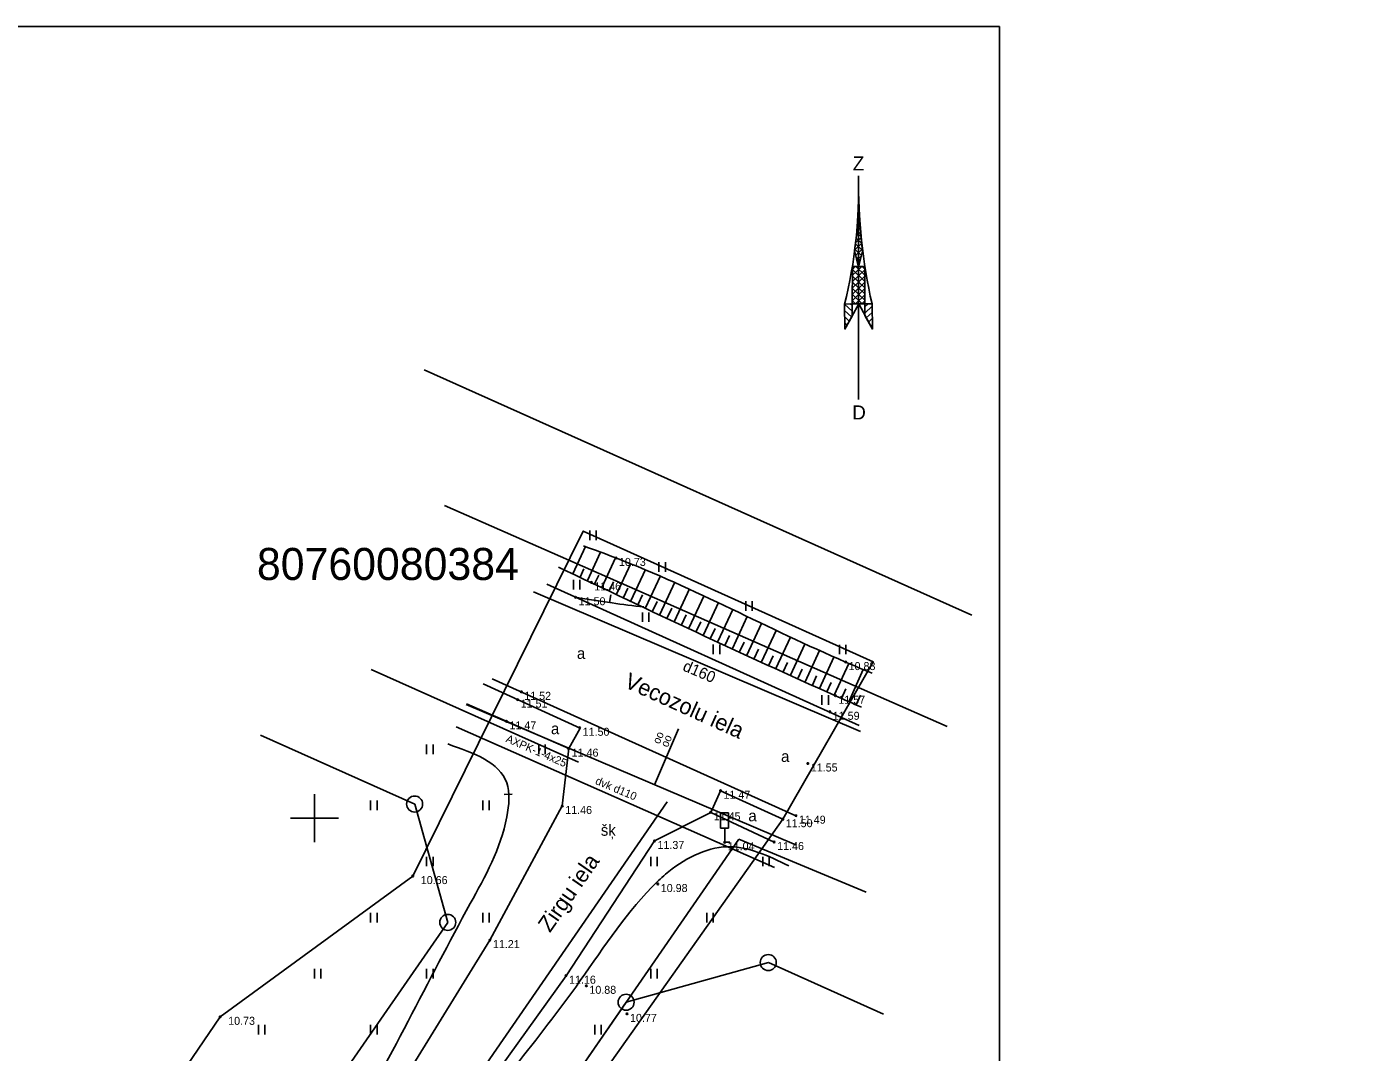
# Model space of a CAD drawing. Extents: x 503353 to 504004, y 304662 to 305049.
# Drawn here: x 503632 to 503715.2, y 304985.4 to 305049.4 of the extents above; entities that cross this region are included whole.
import ezdxf

# ---------------------------------------------------------------- set-up
doc = ezdxf.new("R2010")
doc.units = 0
for name, color, linetype in [('24', 7, 'Continuous'), ('25', 7, 'Continuous'), ('59', 7, 'Continuous'), ('APGR_ELEM_####_####_#', 7, 'Continuous'), ('APGR_SARK_####_####_#', 7, 'Continuous'), ('APGS_ACRL_####_####_#', 7, 'Continuous'), ('APGS_VADP_ZSPR_####_#', 7, 'Continuous'), ('APGS_VADP_ZSPR_TKST_#', 7, 'Continuous'), ('CELI_CMAL_####_####_#', 7, 'Continuous'), ('CELI_CSEG_####_TKST_#', 7, 'Continuous'), ('CELI_ELEM_####_####_#', 7, 'Continuous'), ('CELI_IELA_####_TKST_#', 7, 'Continuous'), ('CELI_SEGL_####_####_#', 7, 'Continuous'), ('GEOD_ELEM_####_####_#', 7, 'Continuous'), ('RAMI_PLAN_####_TKST_#', 7, 'Continuous'), ('RAMI_UZMR_####_####_#', 7, 'Continuous'), ('RELJ_AATZ_####_TKST_#', 7, 'Continuous'), ('RELJ_ELEM_####_####_#', 7, 'Continuous'), ('RELJ_HORZ_PAMT_####_#', 7, 'Continuous'), ('RELJ_NOGA_####_####_#', 7, 'Continuous'), ('RELJ_NOGL_####_####_#', 7, 'Continuous'), ('SAKK_IZVK_####_TKST_#', 7, 'Continuous'), ('SAKK_KKAN_####_####_#', 7, 'Continuous'), ('TERT_ELEM_####_####_#', 7, 'Continuous'), ('UDTK_VADP_UDEN_####_#', 7, 'Continuous'), ('UDTK_VADP_UDEN_TKST_#', 7, 'Continuous')]:
    doc.layers.add(name, color=color, linetype=linetype)

msp = doc.modelspace()

# ---------------------------------------------------------------- linework, layer by layer
at = {"layer": '24'}
for p, q in [((503653.541, 305009.291), (503666.475, 305003.51)), ((503655.169, 304967.847), (503676.504, 304998.703)), ((503676.504, 304998.703), (503684.443, 304995.386))]:
    msp.add_line(p, q, dxfattribs=at)
at = {"layer": '25'}
for p, q in [((503658.122, 305019.539), (503689.517, 305005.723)), ((503672.032, 305001.026), (503595.592, 304890.48))]:
    msp.add_line(p, q, dxfattribs=at)
at = {"layer": 'APGR_ELEM_####_####_#'}
for centre in [(503656.25, 305000.89), (503658.32, 304993.5), (503678.34, 304990.99), (503669.46, 304988.51)]:
    msp.add_circle(centre, 0.5, dxfattribs=at)
at = {"layer": 'APGR_SARK_####_####_#'}
for p, q in [((503656.846, 305028.015), (503691.055, 305012.69)), ((503646.625, 305005.199), (503656.252, 305000.886)), ((503658.316, 304993.498), (503656.252, 305000.886)), ((503595.509, 304902.665), (503658.316, 304993.498)), ((503678.343, 304990.99), (503669.455, 304988.508)), ((503678.343, 304990.99), (503685.526, 304987.772)), ((503669.455, 304988.508), (503606.367, 304897.269))]:
    msp.add_line(p, q, dxfattribs=at)
at = {"layer": 'APGS_ACRL_####_####_#'}
msp.add_line((503678.721, 304996.933), (503658.853, 305005.718), dxfattribs=at)
at = {"layer": 'APGS_VADP_ZSPR_####_#'}
msp.add_line((503678.721, 304996.933), (503658.853, 305005.718), dxfattribs=at)
at = {"layer": 'CELI_CMAL_####_####_#'}
for points in [[(503664.508, 305014.617), (503684.019, 305005.802)], [(503661.094, 305008.716), (503680.064, 305000.162)], [(503659.487, 305007.152), (503665.873, 305004.349)], [(503605.515, 304909.352), (503607.775, 304912.97), (503627.397, 304941.5), (503635.622, 304953.341), (503652.6, 304978.844), (503660.954, 304992.392), (503665.471, 305000.768), (503665.873, 305004.349)], [(503674.743, 305000.37), (503671.232, 304998.583), (503665.707, 304990.166), (503656.075, 304976.73), (503638.511, 304950.933)], [(503674.743, 305000.37), (503678.708, 304998.517)]]:
    msp.add_lwpolyline(points, dxfattribs=at)
at = {"layer": 'CELI_ELEM_####_####_#'}
for p, q in [((503675.864, 305000.348), (503675.364, 305000.348)), ((503675.364, 304999.379), (503675.364, 305000.348)), ((503675.864, 304999.379), (503675.864, 305000.348)), ((503675.864, 304999.379), (503675.364, 304999.379)), ((503675.618, 304999.379), (503675.618, 304998.501)), ((503675.618, 304998.501), (503675.933, 304998.501))]:
    msp.add_line(p, q, dxfattribs=at)
at = {"layer": 'CELI_SEGL_####_####_#'}
for points in [[(503660.523, 305008.403), (503666.595, 305005.618), (503665.873, 305004.349)], [(503679.244, 304999.942), (503675.357, 305001.719), (503674.743, 305000.37)]]:
    msp.add_lwpolyline(points, dxfattribs=at)
at = {"layer": 'GEOD_ELEM_####_####_#'}
for p, q in [((503650, 305001.5), (503650, 305000)), ((503648.5, 305000), (503650, 305000)), ((503650, 305000), (503650, 304998.5)), ((503650, 305000), (503651.5, 305000))]:
    msp.add_line(p, q, dxfattribs=at)
at = {"layer": 'RAMI_PLAN_####_TKST_#'}
for p, q in [((503683.972, 305040.12), (503683.972, 305026.15)), ((503683.976, 305038.419), (503683.998, 305038.397)), ((503683.904, 305037.21), (503684.051, 305037.343)), ((503683.93, 305037.618), (503684.032, 305037.717)), ((503683.933, 305037.682), (503684.04, 305037.579)), ((503683.95, 305038.027), (503684.013, 305038.086)), ((503683.952, 305038.049), (503684.017, 305037.989)), ((503683.837, 305036.365), (503684.11, 305036.627)), ((503683.856, 305036.591), (503684.136, 305036.323)), ((503683.872, 305036.79), (503684.08, 305036.986)), ((503683.885, 305036.951), (503684.102, 305036.745)), ((503683.913, 305037.309), (503684.066, 305037.167)), ((503683.738, 305035.494), (503684.173, 305035.909)), ((503683.78, 305035.884), (503684.224, 305035.461)), ((503683.786, 305035.932), (503684.142, 305036.268)), ((503683.82, 305036.235), (503684.175, 305035.898)), ((503683.742, 305035.536), (503684.156, 305035.139)), ((503683.799, 305035.163), (503684.214, 305035.563)), ((503683.819, 305035.074), (503684.075, 305034.827)), ((503683.872, 305034.846), (503684.148, 305035.109)), ((503683.583, 305033.499), (503684.37, 305034.247)), ((503683.585, 305033.889), (503684.185, 305034.458)), ((503683.59, 305034.279), (503683.776, 305034.458)), ((503683.59, 305034.266), (503684.372, 305033.523)), ((503683.797, 305034.458), (503684.372, 305033.911)), ((503683.934, 305034.572), (503683.993, 305034.516)), ((503683.944, 305034.527), (503684.016, 305034.598)), ((503684.205, 305034.458), (503684.37, 305034.3)), ((503683.575, 305032.712), (503684.372, 305033.473)), ((503683.579, 305033.106), (503684.372, 305033.861)), ((503683.583, 305033.499), (503684.374, 305032.745)), ((503683.585, 305033.879), (503684.374, 305033.134)), ((503683.571, 305032.321), (503684.374, 305033.084)), ((503683.571, 305032.341), (503683.791, 305032.134)), ((503683.575, 305032.728), (503684.2, 305032.134)), ((503683.579, 305033.112), (503684.376, 305032.355)), ((503683.782, 305032.134), (503684.374, 305032.696)), ((503683.102, 305032.1), (503683.124, 305030.551)), ((503683.105, 305032.1), (503683.569, 305031.664)), ((503683.108, 305031.709), (503683.536, 305031.308)), ((503683.124, 305030.551), (503683.985, 305032.125)), ((503683.483, 305032.129), (503683.57, 305032.047)), ((503683.985, 305032.125), (503684.843, 305030.551)), ((503684.188, 305032.134), (503684.376, 305032.311)), ((503684.374, 305031.553), (503684.824, 305031.978)), ((503684.376, 305031.94), (503684.572, 305032.129)), ((503684.462, 305031.245), (503684.827, 305031.597)), ((503684.843, 305030.551), (503684.82, 305032.125)), ((503683.113, 305031.316), (503683.397, 305031.051)), ((503683.12, 305030.921), (503683.256, 305030.792)), ((503684.602, 305030.992), (503684.832, 305031.211)), ((503684.741, 305030.737), (503684.839, 305030.827)), ((503683.124, 305030.558), (503683.134, 305030.567)), ((503684.843, 305030.554), (503684.843, 305030.554))]:
    msp.add_line(p, q, dxfattribs=at)
for points in [[(503692.785, 305049.441), (503692.785, 304852.257), (503550.18, 304852.257), (503550.18, 305049.441)], [(503683.971, 305034.419), (503683.731, 305035.45), (503683.841, 305036.406), (503683.911, 305037.28), (503683.973, 305038.419), (503683.995, 305038.419), (503684.051, 305037.343), (503684.166, 305035.974), (503684.228, 305035.426)], [(503683.591, 305034.458), (503684.37, 305034.458), (503684.376, 305032.132), (503683.57, 305032.136)], [(503683.57, 305032.136), (503683.568, 305031.362), (503683.124, 305030.551), (503683.102, 305032.1)], [(503684.376, 305032.132), (503684.374, 305031.402), (503684.843, 305030.551), (503684.82, 305032.125)]]:
    msp.add_lwpolyline(points, close=True, dxfattribs=at)
for centre, major_axis, start_param, end_param in [((503651.639, 305039.236), (32.345, 0), 6.048896, 6.311872), ((503722.31, 305039.752), (-38.341, 0), 6.273156, 6.494161)]:
    msp.add_ellipse(centre, major_axis=major_axis, ratio=0.950423, start_param=start_param, end_param=end_param, dxfattribs=at)
at = {"layer": 'RAMI_UZMR_####_####_#'}
msp.add_lwpolyline([(503825.923, 304784.828), (503697.433, 304847.709), (503608.51, 304889.842), (503606.524, 304897.202), (503679.244, 304999.942), (503684.897, 305009.76), (503666.777, 305017.939), (503656.134, 304996.39), (503644.103, 304987.6), (503600.987, 304924.263), (503587.985, 304916.668), (503422.237, 304989.372), (503408.615, 305023.495), (503368.776, 305020.183)], dxfattribs=at)
at = {"layer": 'RELJ_ELEM_####_####_#'}
for centre in [(503668.826, 305016.26), (503667.284, 305014.733), (503666.31, 305013.803), (503683.172, 305009.755), (503662.688, 305007.41), (503662.91, 305007.897), (503682.531, 305007.654), (503682.183, 305006.651), (503661.987, 305006.055), (503666.56, 305005.653), (503665.873, 305004.349), (503680.81, 305003.422), (503675.357, 305001.719), (503665.471, 305000.768), (503674.743, 305000.37), (503679.244, 304999.942), (503680.064, 305000.162), (503671.232, 304998.583), (503675.618, 304998.501), (503678.708, 304998.517), (503656.134, 304996.39), (503671.438, 304995.893), (503660.954, 304992.392), (503665.707, 304990.166), (503666.979, 304989.536), (503644.103, 304987.6), (503669.517, 304987.785)]:
    msp.add_circle(centre, 0.05, dxfattribs=at)
at = {"layer": 'RELJ_HORZ_PAMT_####_#'}
for p, q in [((503668.502, 305013.963), (503668.43, 305013.468)), ((503661.834, 305001.49), (503662.334, 305001.498))]:
    msp.add_line(p, q, dxfattribs=at)
for points in [[(503665.225, 305015.689), (503682.531, 305007.654), (503684.157, 305006.937)], [(503666.31, 305013.803), (503668.578, 305013.447), (503670.568, 305013.195)], [(503633.337, 304950.051), (503641.34, 304963.681), (503651.833, 304980), (503659.721, 304994.671), (503662.005, 305000.088), (503662.005, 305002.22), (503658.32, 305004.641)], [(503679.623, 304997.028), (503675.778, 304998.226), (503671.921, 304996.503), (503671.06, 304995.689), (503666.309, 304989.46), (503658.324, 304978.924), (503656.549, 304976.193), (503644.463, 304949.187)]]:
    msp.add_spline(points, degree=3, dxfattribs=at)
at = {"layer": 'RELJ_NOGA_####_####_#'}
for p, q in [((503666.132, 305015.267), (503666.921, 305016.963)), ((503667.038, 305014.845), (503667.864, 305016.615)), ((503667.945, 305014.422), (503668.806, 305016.267)), ((503668.85, 305013.998), (503669.745, 305015.91)), ((503665.225, 305015.689), (503665.226, 305015.69)), ((503665.679, 305015.478), (503665.679, 305015.478)), ((503666.585, 305015.056), (503666.828, 305015.576)), ((503667.492, 305014.634), (503667.745, 305015.176)), ((503669.756, 305013.575), (503670.674, 305015.535)), ((503670.662, 305013.151), (503671.596, 305015.145)), ((503668.398, 305014.21), (503668.661, 305014.774)), ((503669.303, 305013.786), (503669.575, 305014.368)), ((503671.568, 305012.727), (503672.511, 305014.742)), ((503672.473, 305012.303), (503673.421, 305014.328)), ((503670.209, 305013.363), (503670.487, 305013.957)), ((503671.115, 305012.939), (503671.397, 305013.541)), ((503673.379, 305011.879), (503674.326, 305013.905)), ((503674.285, 305011.456), (503675.229, 305013.475)), ((503672.02, 305012.515), (503672.304, 305013.121)), ((503672.926, 305012.091), (503673.211, 305012.699)), ((503675.191, 305011.033), (503676.128, 305013.041)), ((503676.098, 305010.611), (503677.026, 305012.606)), ((503673.832, 305011.667), (503674.116, 305012.274)), ((503674.738, 305011.244), (503675.02, 305011.849)), ((503677.005, 305010.189), (503677.924, 305012.17)), ((503677.912, 305009.769), (503678.822, 305011.737)), ((503675.644, 305010.822), (503675.924, 305011.422)), ((503676.551, 305010.4), (503676.828, 305010.996)), ((503678.82, 305009.35), (503679.723, 305011.307)), ((503679.728, 305008.932), (503680.626, 305010.884)), ((503677.458, 305009.979), (503677.733, 305010.571)), ((503678.366, 305009.559), (503678.637, 305010.148)), ((503680.638, 305008.515), (503681.531, 305010.471)), ((503681.547, 305008.1), (503682.443, 305010.067)), ((503679.274, 305009.141), (503679.544, 305009.727)), ((503680.183, 305008.723), (503680.451, 305009.309)), ((503682.458, 305007.687), (503683.36, 305009.676)), ((503683.372, 305007.281), (503684.255, 305009.3)), ((503681.092, 305008.308), (503681.36, 305008.896)), ((503682.003, 305007.894), (503682.272, 305008.487)), ((503682.914, 305007.483), (503683.18, 305008.085)), ((503683.83, 305007.081), (503684.096, 305007.688))]:
    msp.add_line(p, q, dxfattribs=at)
at = {"layer": 'RELJ_NOGL_####_####_#'}
msp.add_spline([(503666.787, 305017.013), (503668.826, 305016.26), (503683.172, 305009.755), (503684.835, 305009.056)], degree=3, dxfattribs=at)
at = {"layer": 'SAKK_IZVK_####_TKST_#'}
msp.add_line((503672.723, 305005.581), (503671.237, 305002.092), dxfattribs=at)
at = {"layer": 'SAKK_KKAN_####_####_#'}
for points in [[(503676.152, 305000), (503659.477, 305007.099)], [(503680.101, 304998.318), (503676.152, 305000)]]:
    msp.add_lwpolyline(points, dxfattribs=at)
at = {"layer": 'TERT_ELEM_####_####_#'}
for p, q in [((503667.197, 305017.363), (503667.197, 305017.963)), ((503667.597, 305017.363), (503667.597, 305017.963)), ((503671.511, 305015.401), (503671.511, 305016.001)), ((503671.911, 305015.401), (503671.911, 305016.001)), ((503666.172, 305014.284), (503666.172, 305014.884)), ((503666.572, 305014.284), (503666.572, 305014.884)), ((503676.94, 305012.953), (503676.94, 305013.553)), ((503677.34, 305012.953), (503677.34, 305013.553)), ((503670.486, 305012.26), (503670.486, 305012.86)), ((503670.886, 305012.26), (503670.886, 305012.86)), ((503674.903, 305010.257), (503674.903, 305010.857)), ((503675.303, 305010.257), (503675.303, 305010.857)), ((503682.791, 305010.242), (503682.791, 305010.842)), ((503683.191, 305010.242), (503683.191, 305010.842)), ((503681.691, 305007.092), (503681.691, 305007.692)), ((503682.091, 305007.092), (503682.091, 305007.692)), ((503657, 305004), (503657, 305004.6)), ((503657.4, 305004), (503657.4, 305004.6)), ((503664, 305004), (503664, 305004.6)), ((503664.4, 305004), (503664.4, 305004.6)), ((503653.5, 305000.5), (503653.5, 305001.1)), ((503653.9, 305000.5), (503653.9, 305001.1)), ((503660.5, 305000.5), (503660.5, 305001.1)), ((503660.9, 305000.5), (503660.9, 305001.1)), ((503657, 304997), (503657, 304997.6)), ((503657.4, 304997), (503657.4, 304997.6)), ((503671, 304997), (503671, 304997.6)), ((503671.4, 304997), (503671.4, 304997.6)), ((503678, 304997), (503678, 304997.6)), ((503678.4, 304997), (503678.4, 304997.6)), ((503653.5, 304993.5), (503653.5, 304994.1)), ((503653.9, 304993.5), (503653.9, 304994.1)), ((503660.5, 304993.5), (503660.5, 304994.1)), ((503660.9, 304993.5), (503660.9, 304994.1)), ((503674.5, 304993.5), (503674.5, 304994.1)), ((503674.9, 304993.5), (503674.9, 304994.1)), ((503650, 304990), (503650, 304990.6)), ((503650.4, 304990), (503650.4, 304990.6)), ((503657, 304990), (503657, 304990.6)), ((503657.4, 304990), (503657.4, 304990.6)), ((503671, 304990), (503671, 304990.6)), ((503671.4, 304990), (503671.4, 304990.6)), ((503646.5, 304986.5), (503646.5, 304987.1)), ((503646.9, 304986.5), (503646.9, 304987.1)), ((503653.5, 304986.5), (503653.5, 304987.1)), ((503653.9, 304986.5), (503653.9, 304987.1)), ((503667.5, 304986.5), (503667.5, 304987.1)), ((503667.9, 304986.5), (503667.9, 304987.1))]:
    msp.add_line(p, q, dxfattribs=at)
at = {"layer": 'UDTK_VADP_UDEN_####_#'}
msp.add_line((503684.094, 305005.415), (503663.669, 305014.152), dxfattribs=at)

# ---------------------------------------------------------------- texts
at = {"layer": '59'}
msp.add_text('80760080384', height=2, dxfattribs=at).set_placement((503646.398, 305014.883))
at = {"layer": 'APGS_VADP_ZSPR_TKST_#'}
for s, rotation, p in [('AXPK-1-4x25', 336.56819, (503661.901, 305004.791)), ('dvk d110', 337.07876, (503667.493, 305002.158))]:
    msp.add_text(s, height=0.5, rotation=rotation, dxfattribs=at).set_placement(p)
at = {"layer": 'CELI_CSEG_####_TKST_#'}
for s, p in [('a', (503666.385, 305009.955)), ('a', (503664.765, 305005.252)), ('a', (503679.136, 305003.522)), ('a', (503677.093, 304999.81)), ('šķ', (503667.877, 304998.908))]:
    msp.add_text(s, height=0.7, dxfattribs=at).set_placement(p)
at = {"layer": 'CELI_IELA_####_TKST_#'}
for s, rotation, p in [('Vecozolu iela', 335.72866, (503669.277, 305008.215)), ('Zirgu iela', 55.21537, (503664.702, 304992.814))]:
    msp.add_text(s, height=1, rotation=rotation, dxfattribs=at).set_placement(p)
at = {"layer": 'RAMI_PLAN_####_TKST_#'}
for s, p in [('Z', (503683.618, 305040.461)), ('D', (503683.584, 305024.907))]:
    msp.add_text(s, height=0.878, rotation=360, dxfattribs=at).set_placement(p)
at = {"layer": 'RELJ_AATZ_####_TKST_#'}
for s, p in [(' 10.73', (503668.826, 305015.76)), (' 11.46', (503667.284, 305014.233)), (' 11.50', (503666.31, 305013.303)), (' 10.88', (503683.172, 305009.255)), (' 11.51', (503662.688, 305006.91)), (' 11.52', (503662.91, 305007.397)), (' 11.57', (503682.531, 305007.154)), (' 11.59', (503682.183, 305006.151)), (' 11.47', (503661.987, 305005.555)), (' 11.50', (503666.56, 305005.153)), (' 11.46', (503665.873, 305003.849)), (' 11.55', (503680.81, 305002.922)), (' 11.47', (503675.357, 305001.219)), (' 11.46', (503665.471, 305000.268)), (' 11.45', (503674.743, 304999.87)), (' 11.50', (503679.244, 304999.442)), (' 11.49', (503680.064, 304999.662)), (' 11.37', (503671.232, 304998.083)), (' 11.04', (503675.618, 304998.001)), (' 11.46', (503678.708, 304998.017)), ('10.66', (503656.634, 304995.89)), (' 10.98', (503671.438, 304995.393)), (' 11.21', (503660.954, 304991.892)), (' 11.16', (503665.707, 304989.666)), (' 10.88', (503666.979, 304989.036)), ('10.73', (503644.603, 304987.1)), (' 10.77', (503669.517, 304987.285))]:
    msp.add_text(s, height=0.5, dxfattribs=at).set_placement(p)
at = {"layer": 'SAKK_IZVK_####_TKST_#'}
for p in [(503671.546, 305004.597), (503672.054, 305004.393)]:
    msp.add_text('oo', height=0.5, rotation=66.93797, dxfattribs=at).set_placement(p)
at = {"layer": 'UDTK_VADP_UDEN_TKST_#'}
msp.add_text('d160', height=0.7, rotation=336.84001, dxfattribs=at).set_placement((503672.942, 305009.251))

doc.saveas('drawing.dxf')
